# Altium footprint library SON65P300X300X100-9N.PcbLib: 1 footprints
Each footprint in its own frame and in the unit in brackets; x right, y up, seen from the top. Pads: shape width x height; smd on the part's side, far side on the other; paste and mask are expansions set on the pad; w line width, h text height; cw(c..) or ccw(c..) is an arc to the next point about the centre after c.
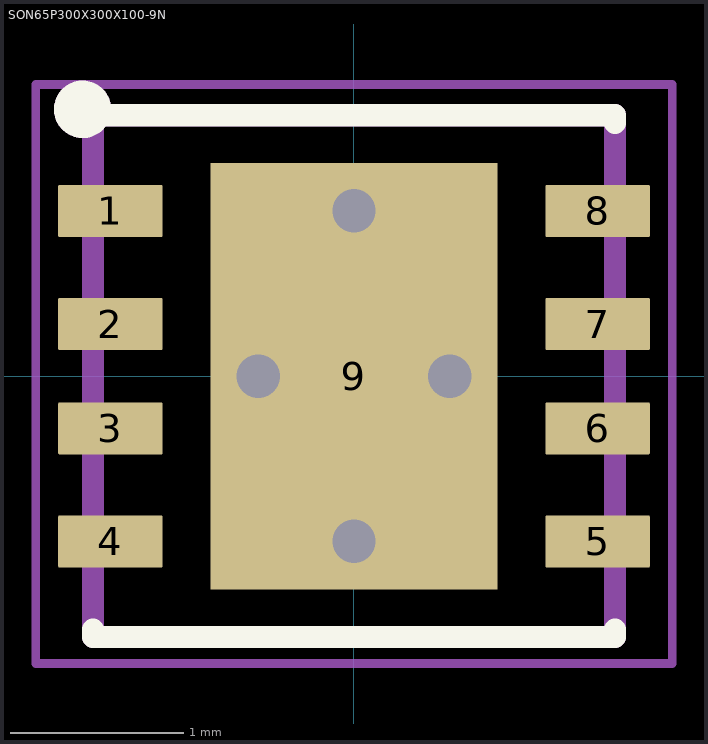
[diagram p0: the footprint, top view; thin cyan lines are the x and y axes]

## SON65P300X300X100-9N [mm]
pads (9):
  rrect5% 0.6x0.3 smd paste+0: 1(-1.4,0.95) 2(-1.4,0.3) 3(-1.4,-0.3) 4(-1.4,-0.95) 5(1.4,-0.95) 6(1.4,-0.3) 7(1.4,0.3) 8(1.4,0.95)
  rect 1.65x2.45 smd: 9(0,0)
via 0,0.95 diameter 0.451 hole 0.25
via 0,-0.95 diameter 0.451 hole 0.25
via 0.55,0 diameter 0.451 hole 0.25
via -0.55,0 diameter 0.451 hole 0.25
Top Overlay:
  circle w0.178: c-1.56,1.534 r0.076
  lines w0.127: -1.5,-1.455 -1.5,-1.5 1.5,-1.5 1.5,-1.455 ; -1.5,1.455 -1.5,1.5 1.5,1.5 1.5,1.455
Assembly Top:
  circle w0.178: c-1.56,1.534 r0.076
  lines w0.127: -1.5,-1.5 1.5,-1.5 1.5,1.5 -1.5,1.5 -1.5,-1.5
Courtyard Top:
  lines w0.05: -1.829,-1.651 -1.829,1.676 1.829,1.676 1.829,-1.651 -1.829,-1.651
